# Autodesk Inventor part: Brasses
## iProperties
Created: 2002-02
Part Number: Brasses
Document SubType Name: Modeling
Designer: ***
Control State: 0
Master: False
Checked Out: False
Shininess: 77.0
Length Units: 11269
Angle Units: 11279
Time Units: 11290
Mass Units: 11283
Length Display Precision: 3
Angle Display Precision: 2
Density: 0.0
Volumn: 0.0
Area: 0.0
PropertySet Name: Model Information
Author: ***
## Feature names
1. Revolution1
2. Hole1
3. Extrusion1
4. Hole2
